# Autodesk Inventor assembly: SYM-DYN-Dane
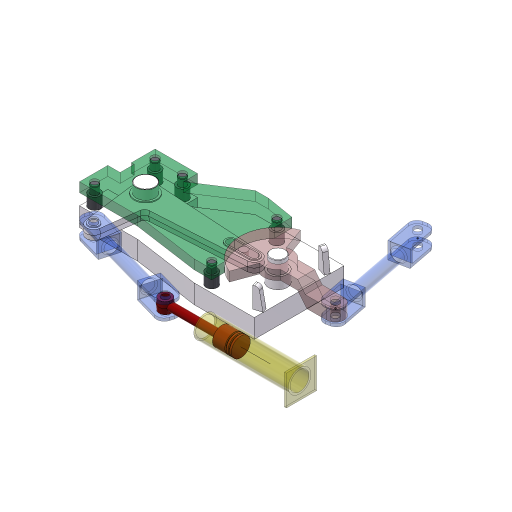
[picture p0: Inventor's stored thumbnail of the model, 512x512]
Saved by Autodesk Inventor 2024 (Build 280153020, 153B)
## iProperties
Company: ATC
Shininess: 64.0
Angle Display Precision: 2
Document Length Units: 11269
Document Angle Units: 11279
Document Time Units: 11290
Document Mass Units: 11283
Document Length Units Precision: 3
Document Angle Units Precision: 2
Created: 2023-03
Part Number: SYM-DYN-Dane
Document SubType Name: Zespół
Designer: Andrzej Jaskulski
Stock Number: SYM-DYN
Checked By: A.J.
Engr Approved By: Andrzej Jaskulski
Mfg Approved By: Andrzej Jaskulski
Authority: A.J.
Density: 0.0
Volumn: 0.0
Area: 0.0
PropertySet Name: Model Information
Control State: 0
Master: False
Checked Out: False
Title: A.J.: Kurs R2024-MEP
Author: Andrzej Jaskulski
Revision Number: 1/24
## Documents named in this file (9)
- C:\Users\AndJas\Documents\R2024-MEP\Obszar roboczy\SPEC-ANALIZY\SYM-DYN-Dane.iam
- C:\Users\AndJas\Documents\R2024-MEP\Obszar roboczy\SPEC-ANALIZY\Płyta górna.ipt
- C:\Users\AndJas\Documents\R2024-MEP\Obszar roboczy\SPEC-ANALIZY\Dźwignia kątowa.ipt
- C:\Users\AndJas\Documents\R2024-MEP\Obszar roboczy\SPEC-ANALIZY\Kołek.ipt
- C:\Users\AndJas\Documents\R2024-MEP\Obszar roboczy\SPEC-ANALIZY\Płyta dolna.ipt
- C:\Users\AndJas\Documents\R2024-MEP\Obszar roboczy\SPEC-ANALIZY\Wahacz.ipt
- C:\Users\AndJas\Documents\R2024-MEP\Obszar roboczy\SPEC-ANALIZY\Łącznik.ipt
- C:\Users\AndJas\Documents\R2024-MEP\Obszar roboczy\SPEC-ANALIZY\Suwak.ipt
- C:\Users\AndJas\Documents\R2024-MEP\Obszar roboczy\SPEC-ANALIZY\Korpus.ipt
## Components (13 placed, 8 different names)
1. Płyta dolna:1 — Zestawiające:1, Zestawiające:2, Zestawiające:3, Napędowe, Zestawiające:4, Zestawiające:5, Suwak2, Zestawiający:13, Zestawiający:14, Kąt:2, Równoległy:1, Zestawiający:15
2. Płyta górna:1 — Wstawiające:6, Zestawiające:4, Wstaw:9, Wstaw:10, Wstaw:11, Wstaw:12
3. Kołek:1 — Wstaw:9
4. Kołek:2 — Wstawiające:6
5. Kołek:3 — Wstaw:10
6. Kołek:4 — Wstaw:11
7. Kołek:5 — Wstaw:12
8. Dźwignia kątowa:1 — Zestawiające:3, Przejściowy:1, Zestawiające:5, Wstaw:13
9. Łącznik:1 — Suwak2, Walec2
10. Wahacz:1 — Zestawiające:1, Zestawiające:2, Przejściowy:1, Napędowe, Walec2
11. Łącznik:2 — Wstaw:13, Zestawiający:16
12. Suwak:1 — Zestawiający:13, Zestawiający:15, Zestawiający:16
13. Korpus:1 — Zestawiający:14, Kąt:2, Równoległy:1
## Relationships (21: Mate 11, Insert 6, Angle 2, Transitional 1, Flush 1)
- Zestawiające:1 [Mate]: Płyta dolna:1 ↔ Wahacz:1
- Zestawiające:2 [Mate]: Płyta dolna:1 ↔ Wahacz:1
- Zestawiające:3 [Mate]: Płyta dolna:1 ↔ Dźwignia kątowa:1
- Przejściowy:1 [Transitional]: Dźwignia kątowa:1 ↔ Wahacz:1
- Napędowe [Angle]: Płyta dolna:1 ↔ Wahacz:1
- Wstawiające:6 [Insert]: Płyta górna:1 ↔ Kołek:2
- Zestawiające:4 [Mate]: Płyta dolna:1 ↔ Płyta górna:1
- Zestawiające:5 [Mate]: Płyta dolna:1 ↔ Dźwignia kątowa:1
- Suwak2 [Mate]: Płyta dolna:1 ↔ Łącznik:1
- Walec2 [Mate]: Łącznik:1 ↔ Wahacz:1
- Wstaw:9 [Insert]: Płyta górna:1 ↔ Kołek:1
- Wstaw:10 [Insert]: Płyta górna:1 ↔ Kołek:3
- Wstaw:11 [Insert]: Płyta górna:1 ↔ Kołek:4
- Wstaw:12 [Insert]: Płyta górna:1 ↔ Kołek:5
- Zestawiający:13 [Mate]: Płyta dolna:1 ↔ Suwak:1
- Zestawiający:14 [Mate]: Płyta dolna:1 ↔ Korpus:1
- Kąt:2 [Angle]: Płyta dolna:1 ↔ Korpus:1
- Równoległy:1 [Flush]: Płyta dolna:1 ↔ Korpus:1
- Wstaw:13 [Insert]: Dźwignia kątowa:1 ↔ Łącznik:2
- Zestawiający:15 [Mate]: Płyta dolna:1 ↔ Suwak:1
- Zestawiający:16 [Mate]: Łącznik:2 ↔ Suwak:1
